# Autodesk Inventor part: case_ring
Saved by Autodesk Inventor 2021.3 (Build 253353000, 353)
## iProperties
Created: 2023-07
Part Number: case_ring
Material: Generic
Document SubType Name: Modeling
Designer: AdminForWorker
Density: 1 g/cm^3
Appearance: Default
Title: case_ring
Author: AdminForWorker
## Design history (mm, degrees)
feature "case_ring"
body "Solid1"
